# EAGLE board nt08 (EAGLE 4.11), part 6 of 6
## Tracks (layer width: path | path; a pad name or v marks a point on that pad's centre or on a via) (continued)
WR_EN\  (via drill 0.61) (continued)
  Bottom 0.254: v487.68,147.96 490.86,151.13 520.7,151.13 522.61,149.22 IC115.5 | v518.79,214 522.61,214 525.14,211.46 IC116.9 | v2.54,321.31 3.81,322.58 181.61,322.58 186.06,318.13 336.55,318.13 339.73,321.31 468.63,321.31 473.07,316.87 v483.87,316.87 | v485.14,243.84 512.45,243.84 IC117.1
WRITE_ALL  (via drill 0.61)
  Top 0.254: v3.81,535.3 3.81,542.29 0,546.1 IC7.11 | v276.23,522.61 276.86,521.97 276.86,478.79 IC68.13 | v330.83,1.91 332.11,3.17 332.11,74.93 335.28,78.11 335.28,183.51 334.01,184.78 v334.01,205.1 | v290.83,217.81 290.83,247.65 288.93,249.56 289.56,250.19 289.56,257.18 288.93,257.81 288.93,272.42 291.46,274.95 291.46,293.37 290.83,294 290.83,338.45 292.1,339.73 292.1,433.7 289.56,436.25 289.56,445.13 288.93,445.77 288.93,466.73 290.83,468.63 v290.83,475.62
  Bottom 0.254: v3.81,535.3 4.45,535.94 73.66,535.94 78.11,540.38 258.44,540.38 v276.23,522.61 276.86,521.97 286.38,521.97 288.29,520.07 421.64,520.07 424.81,523.24 562.61,523.24 567.05,527.68 IC125.8 | v330.83,1.91 327.02,1.91 325.75,3.17 IC70.9 | v334.01,205.1 332.74,206.38 302.26,206.38 v290.83,217.81 | v290.83,475.62 278.76,475.62 277.5,476.88 IC68.13
WRITE_ALL\
  Top 0.254: IC124.6 558.8,422.91 562.61,426.72 562.61,518.16 563.88,519.43 563.88,525.78 565.15,527.05 IC125.9
WRITE_DATA  (via drill 0.61)
  Top 0.254: v280.67,516.25 280.67,472.44 281.94,471.17 IC68.4 | IC70.2 314.96,-2.54 313.69,-1.27 313.69,26.67 320.04,33.02 IC71.4 319.4,34.92 v314.96,39.37 | v293.37,468 294.64,466.73 v294.64,304.17 | v182.88,303.53 181.61,302.26 181.61,194.31 180.97,193.68 180.97,158.75 185.42,154.31 185.42,101.6 186.06,100.97 v186.06,48.26
  Bottom 0.254: v280.67,516.25 281.31,515.62 445.13,515.62 452.12,522.61 563.25,522.61 564.51,521.34 IC125.6 | v314.96,39.37 273.05,39.37 264.16,48.26 v186.06,48.26 80.64,48.26 66.04,62.87 47.62,62.87 46.35,61.59 IC10.9 | v293.37,468 283.85,468 282.57,469.26 IC68.4 | v294.64,304.17 294,303.53 v182.88,303.53
WRITE_DATA\  (via drill 0.61)
  Top 0.254: v283.21,133.35 283.21,119.38 IC60.10 | v359.41,197.49 v359.41,140.34 | v556.89,227.97 556.26,228.6 556.26,420.37 IC124.5 556.26,422.91 557.53,424.18 557.53,514.35 562.61,519.43 IC125.5
  Bottom 0.254: v283.21,133.35 290.19,140.34 v359.41,140.34 | v359.41,197.49 361.31,199.39 528.32,199.39 v556.89,227.97
WRITE_OK  (via drill 0.61)
  Top 0.254: v69.22,142.24 69.22,149.86 59.05,160.02 59.05,164.47 58.42,165.1 58.42,284.48 v57.15,285.75 58.42,287.02 v58.42,327.02 | v346.07,509.9 325.75,489.58 325.75,370.2 322.58,367.03 IC78.10 322.58,364.49 321.31,363.22 321.31,344.17 v320.04,342.9
  Bottom 0.254: v57.15,285.75 8.89,285.75 3.17,291.46 IC2.5 | v69.22,142.24 77.47,133.99 85.72,133.99 87,132.72 M916_6.D2 | v346.07,509.9 366.39,509.9 367.67,508.63 508.63,508.63 516.25,516.25 523.88,516.25 525.14,517.52 IC122.9 | v58.42,327.02 71.12,339.73 125.09,339.73 127,341.63 203.84,341.63 205.1,342.9 v320.04,342.9
WRITE_OK+UTS
  Top 0.254: IC70.13 315.6,3.17 321.94,-3.17 IC70.5
WRITE_OK\  (via drill 0.61)
  Top 0.254: v36.83,131.44 36.83,120.65 35.56,119.38 IC11.13 | v86.36,150.5 91.44,155.57 91.44,210.19 92.71,211.46 92.71,217.17 93.98,218.44 93.98,219.07 92.71,220.34 92.71,234.31 94.61,236.22 94.61,281.94 95.89,283.21 95.89,298.45 102.87,305.44 v102.87,316.23 | v372.11,320.04 380.37,328.3 380.37,455.3 381,455.93 381,492.76 v398.78,510.54
  Bottom 0.254: v36.83,131.44 55.88,150.5 v86.36,150.5 | v102.87,316.23 104.14,317.5 337.19,317.5 339.73,320.04 v372.11,320.04 | v398.78,510.54 401.32,513.08 505.46,513.08 512.45,520.07 526.41,520.07 527.68,518.79 IC122.8
WRTM  (via drill 0.61)
  Top 0.254: v1.27,297.18 1.27,311.79 0.64,312.42 0.64,321.31 2.54,323.21 v2.54,327.02 | IC104.1 472.44,7.62 473.71,8.89 473.71,353.06 v473.07,353.69 472.44,354.33 472.44,375.92 IC110.1 472.44,378.46 473.71,379.73 473.71,389.89 478.79,394.97 478.79,521.34 v483.87,526.41
  Bottom 0.254: v1.27,297.18 -2.54,293.37 IC2.3 | v2.54,327.02 6.35,330.83 59.69,330.83 81.28,352.43 104.78,352.43 105.41,353.06 339.73,353.06 340.36,353.69 v473.07,353.69 | v483.87,526.41 560.71,526.41 561.98,527.68 IC125.10
WRTM+FR03  (via drill 0.61)
  Top 0.254: v274.32,228.6 274.32,185.42 276.86,182.88 276.86,113.03 278.13,111.76 IC60.3 | v475.62,252.09 478.15,254.63 478.15,260.99 478.79,261.62 478.79,267.97 480.06,269.24 IC108.11 | v502.92,278.13 v502.92,379.1
  Bottom 0.254: v274.32,228.6 274.95,229.24 452.75,229.24 v475.62,252.09 | v502.92,379.1 486.41,379.1 486.41,375.92 485.77,375.29 484.5,375.29 483.24,376.56 IC110.5 | v502.92,278.13 497.2,272.42 481.96,272.42 480.69,271.14 IC108.11
WRTM\  (via drill 0.61)
  Top 0.254: IC125.11 560.71,528.96 561.98,530.23 566.42,530.23 566.42,439.42 565.15,438.15 565.15,426.72 561.34,422.91 IC124.7 561.34,420.37 557.53,416.56 557.53,228.6 558.8,227.33 v558.8,11.43 | v274.32,17.78 274.32,107.95 273.05,109.22 IC60.1
  Bottom 0.254: v274.32,17.78 276.86,15.24 430.53,15.24 433.7,12.06 483.24,12.06 484.5,13.34 IC104.9 485.77,14.61 487.05,15.88 488.31,15.88 492.12,12.06 558.16,12.06 v558.8,11.43
XOR_TO_LPB  (via drill 0.61)
  Top 0.254: IC105.3 478.15,43.81 479.43,43.81 IC105.4 | 593.09,577.85 583.57,587.38 445.77,587.38 445.77,586.74 IC103.9 | 593.09,577.85 594.36,576.58 594.36,552.45 608.33,538.48 IC140.8 | v574.67,86.36 581.02,92.71 581.02,565.78 593.09,577.85
  Bottom 0.254: IC103.12 438.79,584.84 440.06,583.57 443.87,583.57 445.13,584.84 IC103.9 | v574.67,86.36 538.48,50.16 485.77,50.16 480.69,45.09 IC105.4
XSA_DY  (via drill 0.61)
  Top 0.254: IC76.11 320.04,250.19 320.04,247.65 317.5,245.11 IC76.3 316.87,243.21 316.87,210.82 v317.5,210.19 | v471.17,41.27 462.28,50.16 v462.28,202.56 | v10.79,445.13 13.34,442.6 v13.34,308.61 | v305.44,303.53 306.07,302.89 v306.07,252.73
  Bottom 0.254: v471.17,41.27 480.69,31.75 567.69,31.75 567.69,24.13 IC123.8 | v462.28,202.56 459.11,205.74 339.09,205.74 334.64,210.19 v317.5,210.19 | v10.79,445.13 4.45,445.13 0.64,448.94 IC5.11 | v13.34,308.61 17.14,304.8 157.48,304.8 158.75,306.07 253.37,306.07 254.63,304.8 294,304.8 294.64,305.44 303.53,305.44 v305.44,303.53 | v306.07,252.73 306.7,253.37 318.13,253.37 319.4,252.09 IC76.11
XSAD
  Top 0.254: IC9.5 43.18,16.51 42.55,17.14 42.55,20.95 41.91,21.59 41.91,121.92 42.55,122.56 42.55,184.78 41.91,185.42 41.91,363.22 43.18,364.49 IC14.10
XSAD\  (via drill 0.61)
  Top 0.254: v-20.32,335.92 -21.59,334.64 -21.59,226.69 -16.51,221.62 -14.61,221.62 M916_19.L2
  Bottom 0.254: v-20.32,335.92 5.71,335.92 32.38,362.58 37.47,362.58 40.01,365.12 IC14.11
XSTA  (via drill 0.61)
  Top 0.254: IC55.12 236.85,518.79 232.41,523.24 232.41,528.32 IC56.1 232.41,530.86 232.41,531.5 233.68,532.76 233.68,565.15 232.41,566.42 IC57.1 | v488.95,419.74 489.58,419.1 489.58,286.38 v487.68,284.48 | v393.7,516.89 413.38,497.2 v413.38,424.81 | M916_19.N2 -8.26,221.62 -10.16,223.52 -10.16,224.16 M916_19.M2 | v287.02,97.79 v282.57,93.34 281.94,92.71 281.94,40.64 284.48,38.1 284.48,-1.27 283.21,-2.54 IC58.5 | v431.8,114.3 431.8,241.3 433.07,242.57 IC94.1 | v13.97,95.25 13.97,124.46 6.35,132.08 6.35,155.57 -3.81,165.74 -3.81,206.38 -4.45,207.01 -4.45,224.16 M916_19.P2 | IC95.5 443.23,280.67 444.5,279.4 444.5,246.38 443.23,245.11 IC94.5
  Bottom 0.254: IC57.1 233.04,567.05 234.31,565.78 240.66,565.78 241.94,567.05 IC57.5 | IC56.1 233.04,530.23 234.31,531.5 240.66,531.5 241.94,530.23 IC56.5 | IC95.1 433.7,281.31 434.98,280.04 441.32,280.04 442.6,281.31 IC95.5 443.87,282.57 445.13,283.85 487.05,283.85 v487.68,284.48 | IC137.11 600.08,422.27 597.53,419.74 v488.95,419.74 486.41,422.27 415.93,422.27 v413.38,424.81 | v393.7,516.89 288.93,516.89 285.12,520.7 240.03,520.7 238.12,518.79 IC55.12 | M916_19.P2 -5.08,224.16 -7.62,221.62 M916_19.N2 | IC58.1 273.69,-3.17 274.95,-1.91 281.31,-1.91 282.57,-3.17 IC58.5 | IC94.1 433.7,244.47 434.98,245.75 441.32,245.75 442.6,244.47 IC94.5 | v287.02,97.79 293.37,104.14 421.64,104.14 v431.8,114.3 | v13.97,95.25 14.61,94.61 100.97,94.61 101.6,93.98 146.69,93.98 147.96,95.25 225.43,95.25 227.33,93.34 v282.57,93.34
XSTA\  (via drill 0.61)
  Top 0.254: 276.86,217.81 v276.86,221.62 | 276.86,217.81 276.86,189.23 275.59,187.96 IC61.2 | v346.71,224.79 349.88,227.97 v349.88,236.22 | v400.05,247.01 400.05,250.19 IC87.11 | M916_19.J2 -20.95,221.62 -22.86,223.52 -22.86,224.16 M916_19.H2 | M916_19.K2 -16.51,224.79 -15.88,225.43 -15.88,232.41 -14.61,233.68 M916_20.L2 -14.61,234.31 -14.61,234.95 -16.51,236.85 M916_20.K2 -16.51,237.49 -15.88,238.12 -15.88,248.28 -17.14,249.56 -17.14,311.15 -18.41,312.42 -18.41,379.73 -11.43,386.71 -11.43,389.25 M916_22.M2 | v233.68,394.33 233.68,515.62 234.95,516.89 IC55.13 | v275.59,217.81 276.86,217.81 | v192.41,217.81 191.13,219.07 191.13,249.56 189.87,250.82 189.87,348.62 189.23,349.25 189.23,391.8 v188.59,392.43
  Bottom 0.254: v276.86,221.62 280.04,224.79 v346.71,224.79 | v349.88,236.22 360.68,247.01 v400.05,247.01 | M916_19.K2 -17.78,224.16 -20.32,221.62 M916_19.J2 | v233.68,394.33 231.78,392.43 v188.59,392.43 103.5,392.43 98.42,397.51 -0.64,397.51 -8.26,389.89 | -8.26,389.89 -10.16,389.89 M916_22.M2 | -8.26,389.89 -8.26,386.71 M916_22.N2 | v192.41,217.81 v275.59,217.81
